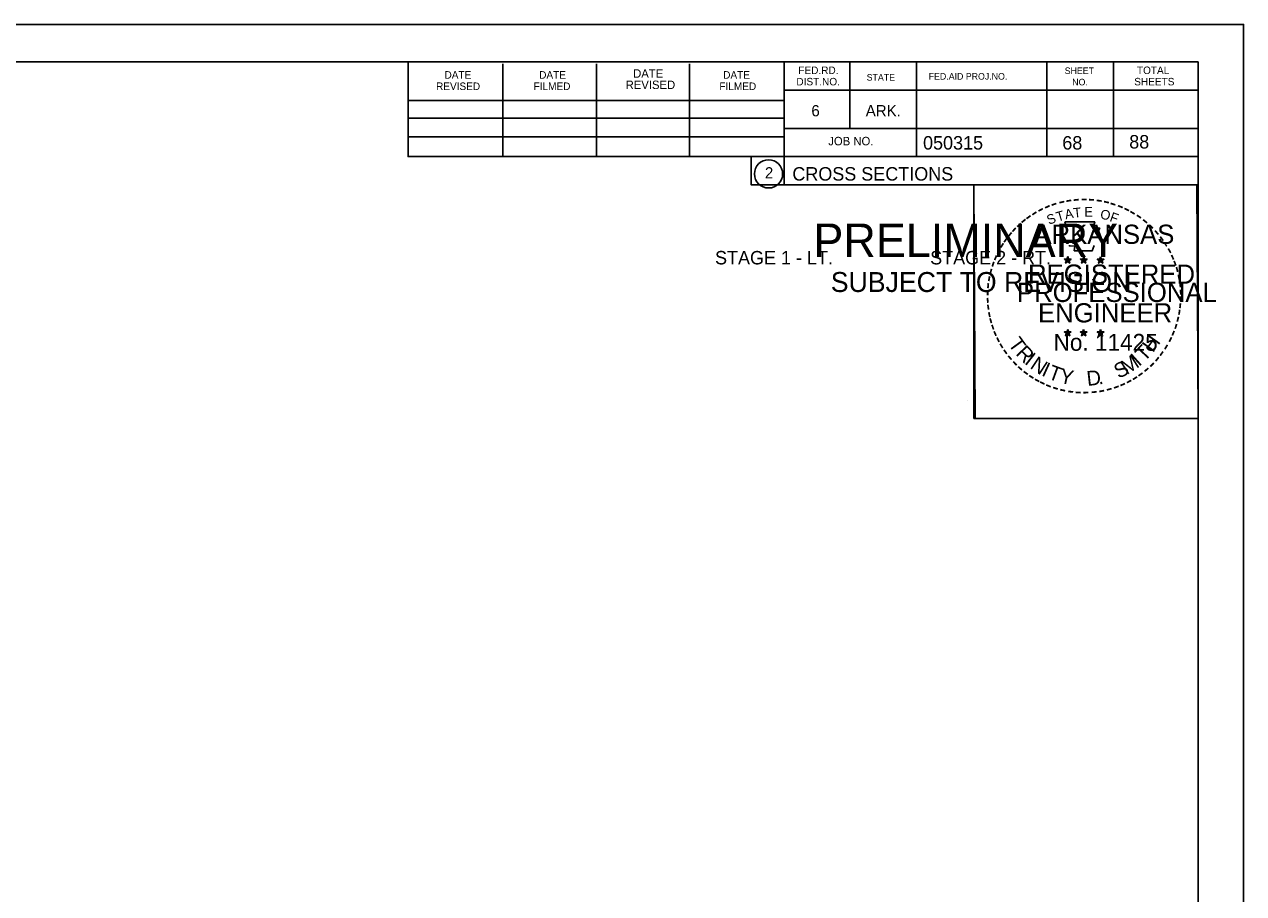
# Model space of a CAD drawing. Extents: x 1486524 to 1499135, y 326561 to 337924.
# Drawn here: x 1489018.9 to 1489145.8, y 332048.8 to 332139.3 of the extents above; entities that cross this region are included whole.
import ezdxf

# ---------------------------------------------------------------- set-up
doc = ezdxf.new("R2010")
doc.units = 0
for name, color, linetype in [('Default', 7, 'Continuous'), ('E_Property Line', 7, 'Continuous'), ('E_Quarter Calls', 7, 'Continuous'), ('E_Section Line', 7, 'Continuous'), ('E_Station Offset', 7, 'Continuous'), ('S_SIXTEEN_SECTION', 7, 'Continuous')]:
    doc.layers.add(name, color=color, linetype=linetype)

msp = doc.modelspace()

# ---------------------------------------------------------------- linework, layer by layer
at = {"layer": 'E_Property Line'}
for p, q in [((1488824.89, 332135.4), (1489141.07, 332135.4)), ((1489058.81, 332125.52), (1489058.81, 332135.4)), ((1489068.67, 332125.52), (1489068.67, 332135.2)), ((1489078.43, 332125.52), (1489078.43, 332135.2)), ((1489088.11, 332125.52), (1489088.11, 332135.2)), ((1489097.97, 332135.4), (1489097.97, 332122.6)), ((1489104.81, 332135.4), (1489104.81, 332128.46)), ((1489111.75, 332135.4), (1489111.75, 332125.52)), ((1489125.33, 332135.4), (1489125.33, 332125.52)), ((1489132.27, 332135.4), (1489132.27, 332125.52)), ((1489141.07, 331929.94), (1489141.07, 332135.4)), ((1489058.81, 332131.38), (1489097.97, 332131.38)), ((1489141.07, 332132.46), (1489097.97, 332132.46)), ((1489141.07, 332132.48), (1489141.07, 332132.48)), ((1489058.81, 332129.52), (1489097.97, 332129.52)), ((1489058.81, 332125.52), (1489058.81, 332127.58)), ((1489058.81, 332127.58), (1489097.97, 332127.58)), ((1489141.07, 332128.46), (1489097.97, 332128.46)), ((1489100.93, 332128.46), (1489141.07, 332128.46)), ((1489141.07, 332125.52), (1489058.81, 332125.52)), ((1489097.97, 332122.6), (1489141.07, 332122.6))]:
    msp.add_line(p, q, dxfattribs=at)
msp.add_circle((1489096.35, 332123.73), 1.47, dxfattribs=at)
at = {"layer": 'E_Quarter Calls'}
for p, q in [((1488812.48, 332139.29), (1489145.82, 332139.29)), ((1489117.1, 332100.14), (1489117.1, 332100.14))]:
    msp.add_line(p, q, dxfattribs=at)
for points in [[(1488812.48, 332139.29), (1489145.82, 332139.29), (1489145.82, 331925.95), (1488812.48, 331925.95)], [(1489058.81, 332135.4), (1489058.81, 332125.52), (1489094.54, 332125.52), (1489094.54, 332122.6), (1489117.74, 332122.6), (1489117.74, 332098.26), (1489141.07, 332098.26), (1489141.07, 331929.94), (1488824.89, 331929.94), (1488824.89, 332135.4)], [(1489117.74, 332122.6), (1489140.94, 332122.6), (1489141.07, 332098.26), (1489117.86, 332098.26)]]:
    msp.add_lwpolyline(points, close=True, dxfattribs=at)
at = {"layer": 'S_SIXTEEN_SECTION'}
for p, q in [((1489127.15, 332114.85), (1489127.5, 332114.74)), ((1489127.15, 332114.85), (1489127.4, 332114.81)), ((1489127.15, 332114.85), (1489127.39, 332114.73)), ((1489127.5, 332115.11), (1489127.46, 332114.85)), ((1489127.5, 332114.74), (1489127.5, 332115.11)), ((1489127.5, 332115.11), (1489127.55, 332114.86)), ((1489127.85, 332114.85), (1489127.5, 332114.74)), ((1489127.85, 332114.85), (1489127.56, 332114.8)), ((1489127.85, 332114.85), (1489127.64, 332114.75)), ((1489128.82, 332114.85), (1489129.17, 332114.74)), ((1489128.82, 332114.85), (1489129.07, 332114.81)), ((1489128.82, 332114.85), (1489129.06, 332114.73)), ((1489129.17, 332115.11), (1489129.13, 332114.85)), ((1489129.17, 332114.74), (1489129.17, 332115.11)), ((1489129.17, 332115.11), (1489129.22, 332114.86)), ((1489129.52, 332114.85), (1489129.17, 332114.74)), ((1489129.52, 332114.85), (1489129.23, 332114.8)), ((1489129.52, 332114.85), (1489129.31, 332114.75)), ((1489130.58, 332114.84), (1489130.93, 332114.73)), ((1489130.58, 332114.84), (1489130.84, 332114.8)), ((1489130.58, 332114.84), (1489130.82, 332114.72)), ((1489130.93, 332115.09), (1489130.89, 332114.84)), ((1489130.93, 332114.73), (1489130.93, 332115.09)), ((1489130.93, 332115.09), (1489130.98, 332114.84)), ((1489131.28, 332114.84), (1489130.93, 332114.73)), ((1489131.28, 332114.84), (1489130.99, 332114.79)), ((1489131.28, 332114.84), (1489131.08, 332114.74)), ((1489127.28, 332114.44), (1489127.5, 332114.74)), ((1489127.28, 332114.44), (1489127.41, 332114.69)), ((1489127.28, 332114.44), (1489127.5, 332114.66)), ((1489127.71, 332114.44), (1489127.5, 332114.74)), ((1489127.71, 332114.44), (1489127.5, 332114.66)), ((1489127.71, 332114.44), (1489127.58, 332114.74)), ((1489128.95, 332114.44), (1489129.17, 332114.74)), ((1489128.95, 332114.44), (1489129.08, 332114.69)), ((1489128.95, 332114.44), (1489129.17, 332114.66)), ((1489129.38, 332114.44), (1489129.17, 332114.74)), ((1489129.38, 332114.44), (1489129.17, 332114.66)), ((1489129.38, 332114.44), (1489129.25, 332114.74)), ((1489130.72, 332114.43), (1489130.93, 332114.73)), ((1489130.72, 332114.43), (1489130.84, 332114.68)), ((1489130.72, 332114.43), (1489130.93, 332114.65)), ((1489131.15, 332114.43), (1489130.93, 332114.73)), ((1489131.15, 332114.43), (1489130.93, 332114.65)), ((1489131.15, 332114.43), (1489131.01, 332114.72)), ((1489127.15, 332107.28), (1489127.5, 332107.17)), ((1489127.15, 332107.28), (1489127.4, 332107.23)), ((1489127.15, 332107.28), (1489127.38, 332107.16)), ((1489127.28, 332106.87), (1489127.5, 332107.17)), ((1489127.5, 332107.53), (1489127.45, 332107.28)), ((1489127.5, 332107.17), (1489127.5, 332107.53)), ((1489127.5, 332107.53), (1489127.54, 332107.28)), ((1489127.84, 332107.28), (1489127.5, 332107.17)), ((1489127.71, 332106.87), (1489127.5, 332107.17)), ((1489127.84, 332107.28), (1489127.56, 332107.23)), ((1489127.71, 332106.87), (1489127.57, 332107.16)), ((1489127.84, 332107.28), (1489127.64, 332107.18)), ((1489128.82, 332107.28), (1489129.16, 332107.17)), ((1489128.82, 332107.28), (1489129.07, 332107.23)), ((1489128.82, 332107.28), (1489129.05, 332107.16)), ((1489128.95, 332106.87), (1489129.16, 332107.17)), ((1489129.16, 332107.53), (1489129.12, 332107.28)), ((1489129.16, 332107.17), (1489129.16, 332107.53)), ((1489129.16, 332107.53), (1489129.21, 332107.28)), ((1489129.51, 332107.28), (1489129.16, 332107.17)), ((1489129.38, 332106.87), (1489129.16, 332107.17)), ((1489129.51, 332107.28), (1489129.23, 332107.23)), ((1489129.38, 332106.87), (1489129.24, 332107.16)), ((1489129.51, 332107.28), (1489129.31, 332107.18)), ((1489130.58, 332107.27), (1489130.93, 332107.16)), ((1489130.58, 332107.27), (1489130.84, 332107.22)), ((1489130.58, 332107.27), (1489130.82, 332107.15)), ((1489130.72, 332106.86), (1489130.93, 332107.16)), ((1489130.93, 332107.52), (1489130.89, 332107.27)), ((1489130.93, 332107.16), (1489130.93, 332107.52)), ((1489130.93, 332107.52), (1489130.98, 332107.27)), ((1489131.28, 332107.27), (1489130.93, 332107.16)), ((1489131.14, 332106.86), (1489130.93, 332107.16)), ((1489131.28, 332107.27), (1489130.99, 332107.22)), ((1489131.14, 332106.86), (1489131.01, 332107.15)), ((1489131.28, 332107.27), (1489131.07, 332107.17)), ((1489127.28, 332106.87), (1489127.41, 332107.12)), ((1489127.28, 332106.87), (1489127.49, 332107.09)), ((1489127.71, 332106.87), (1489127.49, 332107.09)), ((1489128.95, 332106.87), (1489129.07, 332107.12)), ((1489128.95, 332106.87), (1489129.16, 332107.09)), ((1489129.38, 332106.87), (1489129.16, 332107.09)), ((1489130.72, 332106.86), (1489130.84, 332107.11)), ((1489130.72, 332106.86), (1489130.93, 332107.08)), ((1489131.14, 332106.86), (1489130.93, 332107.08))]:
    msp.add_line(p, q, dxfattribs=at)
for points in [[(1489127.19, 332118.73), (1489127.46, 332117.9)], [(1489130.7, 332117.81), (1489130.84, 332118.09), (1489130.16, 332118.07), (1489130.31, 332118.73), (1489127.19, 332118.73)], [(1489127.68, 332116.31), (1489127.68, 332116.22), (1489128.25, 332116.2), (1489128.19, 332115.73), (1489130.06, 332115.73), (1489130.26, 332116.26)], [(1489127.5, 332115.11), (1489127.71, 332114.44), (1489127.15, 332114.85), (1489127.85, 332114.85), (1489127.28, 332114.44), (1489127.5, 332115.11)], [(1489129.17, 332115.11), (1489129.38, 332114.44), (1489128.82, 332114.85), (1489129.52, 332114.85), (1489128.95, 332114.44), (1489129.17, 332115.11)], [(1489130.93, 332115.09), (1489131.15, 332114.43), (1489130.58, 332114.84), (1489131.28, 332114.84), (1489130.72, 332114.43), (1489130.93, 332115.09)], [(1489127.5, 332107.53), (1489127.71, 332106.87), (1489127.15, 332107.28), (1489127.84, 332107.28), (1489127.28, 332106.87), (1489127.5, 332107.53)], [(1489129.16, 332107.53), (1489129.38, 332106.87), (1489128.82, 332107.28), (1489129.51, 332107.28), (1489128.95, 332106.87), (1489129.16, 332107.53)], [(1489130.93, 332107.52), (1489131.14, 332106.86), (1489130.58, 332107.27), (1489131.28, 332107.27), (1489130.72, 332106.86), (1489130.93, 332107.52)]]:
    msp.add_lwpolyline(points, dxfattribs=at)
for centre, radius in [((1489127.5, 332114.74), 0.172), ((1489127.5, 332114.74), 0.145), ((1489127.5, 332114.74), 0.116), ((1489127.5, 332114.74), 0.0991), ((1489127.5, 332114.74), 0.0747), ((1489127.5, 332114.74), 0.0495), ((1489127.5, 332114.74), 0.0296), ((1489129.17, 332114.74), 0.172), ((1489129.17, 332114.74), 0.145), ((1489129.17, 332114.74), 0.116), ((1489129.17, 332114.74), 0.0991), ((1489129.17, 332114.74), 0.0747), ((1489129.17, 332114.74), 0.0495), ((1489129.17, 332114.74), 0.0296), ((1489130.93, 332114.73), 0.172), ((1489130.93, 332114.73), 0.145), ((1489130.93, 332114.73), 0.116), ((1489130.93, 332114.73), 0.0991), ((1489130.93, 332114.73), 0.0747), ((1489130.93, 332114.73), 0.0495), ((1489130.93, 332114.73), 0.0296), ((1489127.49, 332107.17), 0.172), ((1489127.49, 332107.17), 0.145), ((1489127.49, 332107.17), 0.116), ((1489127.49, 332107.17), 0.0991), ((1489127.49, 332107.17), 0.0747), ((1489127.49, 332107.17), 0.0495), ((1489127.49, 332107.17), 0.0296), ((1489129.16, 332107.17), 0.172), ((1489129.16, 332107.17), 0.145), ((1489129.16, 332107.17), 0.116), ((1489129.16, 332107.17), 0.0991), ((1489129.16, 332107.17), 0.0747), ((1489129.16, 332107.17), 0.0495), ((1489129.16, 332107.17), 0.0296), ((1489130.93, 332107.16), 0.172), ((1489130.93, 332107.16), 0.145), ((1489130.93, 332107.16), 0.116), ((1489130.93, 332107.16), 0.0991), ((1489130.93, 332107.16), 0.0747), ((1489130.93, 332107.16), 0.0495), ((1489130.93, 332107.16), 0.0296)]:
    msp.add_circle(centre, radius, dxfattribs=at)

# ---------------------------------------------------------------- texts
at = {"layer": 'Default'}
for s, p in [('STAGE 1 - LT.', (1489090.78, 332114.3)), ('STAGE 2 - RT.', (1489113.18, 332114.3))]:
    msp.add_text(s, height=1.4, dxfattribs=at).set_placement(p)
at = {"layer": 'E_Property Line'}
for s, height, p in [('DATE', 0.782, (1489062.61, 332133.64)), ('DATE', 0.782, (1489072.47, 332133.64)), ('DATE', 0.879, (1489082.25, 332133.74)), ('DATE', 0.782, (1489091.63, 332133.64)), ('FED.RD.', 0.782, (1489099.45, 332134.12)), ('STATE', 0.684, (1489106.57, 332133.44)), ('FED.AID PROJ.NO.', 0.684, (1489113.03, 332133.54)), ('SHEET', 0.684, (1489127.19, 332134.12)), ('TOTAL', 0.782, (1489134.71, 332134.12)), ('REVISED', 0.782, (1489061.73, 332132.46)), ('FILMED', 0.782, (1489071.89, 332132.46)), ('REVISED', 0.879, (1489081.47, 332132.56)), ('FILMED', 0.782, (1489091.23, 332132.46)), ('DIST.NO.', 0.782, (1489099.25, 332132.94)), ('NO.', 0.684, (1489127.97, 332132.94)), ('SHEETS', 0.782, (1489134.43, 332132.94)), ('6', 1.17, (1489100.81, 332129.72)), ('ARK.', 1.172, (1489106.47, 332129.72)), ('JOB NO.', 0.879, (1489102.57, 332126.7)), ('050315', 1.4, (1489112.44, 332126.26)), ('2', 1.17, (1489095.97, 332123.25)), ('CROSS SECTIONS', 1.4, (1489098.83, 332123.03))]:
    msp.add_text(s, height=height, rotation=360, dxfattribs=at).set_placement(p)
at = {"layer": 'E_Section Line'}
for s, height, p in [('PRELIMINARY', 3.5, (1489101.02, 332115.06)), ('DWB', 0.01, (1489101.76, 332116.91)), ('SUBJECT TO REVISION', 2.0751, (1489102.83, 332111.43))]:
    msp.add_text(s, height=height, rotation=360, dxfattribs=at).set_placement(p)
at = {"layer": 'E_Station Offset'}
for s, p in [('68', (1489126.94, 332126.26)), ('88', (1489133.91, 332126.37))]:
    msp.add_text(s, height=1.4, dxfattribs=at).set_placement(p)
at = {"layer": 'S_SIXTEEN_SECTION'}
for s, height, rotation, p in [('-', 1.6, 5.8968, (1489128.1, 332120.37)), ('-', 1.6, 0.1862, (1489128.87, 332120.44)), ('-', 1.6, 357.743, (1489129.59, 332120.43)), ('-', 1.6, 34.0636, (1489124.08, 332118.9)), ('-', 1.6, 28.7918, (1489124.67, 332119.27)), ('-', 1.6, 24.3072, (1489125.31, 332119.59)), ('-', 1.6, 19.1761, (1489125.94, 332119.86)), ('T', 1, 16.4036, (1489126.46, 332118.74)), ('-', 1.6, 13.6301, (1489126.69, 332120.1)), ('A', 1, 11.2132, (1489127.29, 332118.99)), ('-', 1.6, 10.2193, (1489127.37, 332120.26)), ('T', 1, 6.0228, (1489128.14, 332119.16)), ('E', 1, 0.8323, (1489129.24, 332119.27)), ('-', 1.6, 352.1617, (1489130.34, 332120.37)), ('O', 1, 350.4515, (1489130.84, 332119.06)), ('-', 1.6, 347.2049, (1489131.05, 332120.26)), ('-', 1.6, 342.3362, (1489131.69, 332120.1)), ('-', 1.6, 337.8551, (1489132.42, 332119.88)), ('-', 1.6, 334.1211, (1489133.06, 332119.61)), ('-', 1.6, 329.6409, (1489133.63, 332119.33)), ('-', 1.6, 42.9622, (1489122.59, 332117.71)), ('-', 1.6, 38.9507, (1489123.02, 332118.13)), ('-', 1.6, 36.2317, (1489123.5, 332118.51)), ('S', 1, 21.594, (1489125.55, 332118.41)), ('F', 1, 340.0707, (1489131.8, 332118.83)), ('-', 1.6, 325.8627, (1489134.28, 332118.97)), ('-', 1.6, 320.5297, (1489134.89, 332118.54)), ('-', 1.6, 50.6142, (1489121.74, 332116.75)), ('-', 1.6, 48.423, (1489122.14, 332117.23)), ('ARKANSAS', 2, 360, (1489124.04, 332116.44)), ('-', 1.6, 315.5786, (1489135.49, 332118.05)), ('-', 1.6, 309.8797, (1489136.06, 332117.5)), ('-', 1.6, 58.0706, (1489121, 332115.65)), ('-', 1.6, 54.2325, (1489121.32, 332116.18)), ('-', 1.6, 306.6522, (1489136.58, 332116.9)), ('-', 1.4, 303.6753, (1489137.07, 332116.33)), ('-', 1.6, 67.7743, (1489120.43, 332114.43)), ('-', 1.6, 62.8713, (1489120.69, 332115.04)), ('-', 1.6, 299.6684, (1489137.39, 332115.73)), ('-', 1.6, 294.6628, (1489137.71, 332115.11)), ('-', 1.6, 75.461, (1489120.01, 332113.08)), ('-', 1.6, 72.3945, (1489120.21, 332113.8)), ('REGISTERED', 2, 360, (1489123.37, 332112.29)), ('DWB', 0.01, 360, (1489127.49, 332114.74)), ('DWB', 0.01, 360, (1489129.16, 332114.74)), ('DWB', 0.01, 360, (1489130.92, 332114.73)), ('-', 1.6, 290.5728, (1489137.97, 332114.54)), ('-', 1.6, 285.1233, (1489138.2, 332113.96)), ('-', 1.6, 85.1863, (1489119.8, 332111.68)), ('-', 1.6, 81.2013, (1489119.88, 332112.37)), ('PROFESSIONAL', 2, 360, (1489122.22, 332110.39)), ('-', 1.6, 280.5493, (1489138.4, 332113.21)), ('-', 1.6, 276.5962, (1489138.56, 332112.45)), ('-', 1.6, 89.0622, (1489119.78, 332110.98)), ('-', 1.6, 274.3301, (1489138.62, 332111.72)), ('-', 1.6, 269.9407, (1489138.66, 332111.09)), ('-', 1.6, 94.1959, (1489119.81, 332110.25)), ('-', 1.6, 98.9479, (1489119.89, 332109.59)), ('ENGINEER', 2, 360, (1489124.41, 332108.26)), ('-', 1.6, 263.5172, (1489138.64, 332110.43)), ('-', 1.6, 101.7149, (1489120.02, 332108.85)), ('-', 1.6, 105.4578, (1489120.18, 332108.26)), ('-', 1.6, 255.7626, (1489138.46, 332109.09)), ('-', 1.6, 260.9953, (1489138.57, 332109.77)), ('-', 1.6, 109.0874, (1489120.4, 332107.63)), ('-', 1.6, 114.0643, (1489120.65, 332107.03)), ('DWB', 0.01, 360, (1489127.48, 332107.16)), ('DWB', 0.01, 360, (1489129.15, 332107.16)), ('DWB', 0.01, 360, (1489130.92, 332107.15)), ('-', 1.6, 247.8887, (1489138.05, 332107.7)), ('-', 1.6, 252.8681, (1489138.28, 332108.37)), ('-', 1.6, 115.7289, (1489120.96, 332106.41)), ('-', 1.6, 120.4471, (1489121.31, 332105.83)), ('T', 1.54, 306.0406, (1489121.25, 332106.01)), ('R', 1.54, 314.005, (1489122.02, 332104.96)), ('No. 11425', 1.757, 360, (1489126.03, 332105.31)), ('T', 1.54, 46.6444, (1489135.49, 332104.1)), ('H', 1.54, 54.6088, (1489136.38, 332105.04)), ('-', 1.6, 239.0712, (1489137.4, 332106.32)), ('-', 1.6, 244.6197, (1489137.79, 332107.07)), ('-', 1.6, 125.8934, (1489121.72, 332105.27)), ('-', 1.6, 130.7181, (1489122.18, 332104.72)), ('I', 1.54, 321.9694, (1489122.92, 332104.03)), ('N', 1.54, 326.5002, (1489123.49, 332103.55)), ('M', 1.54, 32.6563, (1489133.64, 332102.77)), ('I', 1.54, 42.1136, (1489134.92, 332103.62)), ('-', 1.6, 231.2538, (1489136.56, 332105.1)), ('-', 1.6, 233.8452, (1489136.99, 332105.67)), ('-', 1.6, 134.2238, (1489122.7, 332104.17)), ('-', 1.6, 138.9338, (1489123.22, 332103.71)), ('I', 1.54, 335.3603, (1489124.69, 332102.77)), ('T', 1.54, 339.8912, (1489125.35, 332102.44)), ('Y', 1.54, 347.8556, (1489126.57, 332102)), ('S', 1.54, 26.9312, (1489132.8, 332102.37)), ('-', 1.6, 221.0851, (1489135.56, 332104.03)), ('-', 1.6, 225.7653, (1489136.09, 332104.54)), ('-', 1.6, 144.6463, (1489123.78, 332103.3)), ('-', 1.6, 148.0898, (1489124.34, 332102.93)), ('-', 1.6, 151.5704, (1489124.92, 332102.6)), ('-', 1.6, 154.6002, (1489125.44, 332102.36)), ('D', 1.54, 6.3969, (1489129.56, 332101.64)), ('.', 1.54, 13.7642, (1489130.75, 332101.77)), ('-', 1.6, 207.3568, (1489133.92, 332102.82)), ('-', 1.6, 212.2491, (1489134.48, 332103.17)), ('-', 1.6, 215.7363, (1489135.01, 332103.56)), ('-', 1.6, 158.5612, (1489126.06, 332102.1)), ('-', 1.6, 162.7983, (1489126.75, 332101.89)), ('-', 1.6, 167.5555, (1489127.46, 332101.73)), ('-', 1.6, 173.1155, (1489128.24, 332101.62)), ('-', 1.6, 176.5183, (1489128.98, 332101.56)), ('-', 1.6, 181.5918, (1489129.73, 332101.58)), ('-', 1.6, 185.8167, (1489130.54, 332101.66)), ('-', 1.6, 191.2858, (1489131.27, 332101.79)), ('-', 1.6, 195.4743, (1489132, 332101.99)), ('-', 1.6, 200.7184, (1489132.68, 332102.23)), ('-', 1.6, 204.2516, (1489133.3, 332102.5))]:
    msp.add_text(s, height=height, rotation=rotation, dxfattribs=at).set_placement(p)

doc.saveas('drawing.dxf')
